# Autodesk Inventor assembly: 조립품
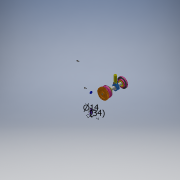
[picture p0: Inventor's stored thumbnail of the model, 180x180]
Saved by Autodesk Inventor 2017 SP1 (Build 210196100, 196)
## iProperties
Part Number: 조립품
Material: 일반
Document SubType Name: Assembly
Designer: 00-00
Author: 00-00
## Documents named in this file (21)
- C:\Users\00-00\Desktop\601206V1010\조립품.iam
- C:\Users\00-00\Desktop\601206V1010\E-링.ipt
- C:\Users\00-00\Desktop\601206V1010\개스킷 A.ipt
- C:\Users\00-00\Desktop\601206V1010\개스킷 B.ipt
- C:\Users\00-00\Desktop\601206V1010\덮개.ipt
- C:\Users\00-00\Desktop\601206V1010\뒤커버.ipt
- C:\Users\00-00\Desktop\601206V1010\링크.ipt
- C:\Users\00-00\Desktop\601206V1010\베어링 17 x 40 x 12.ipt
- C:\Users\00-00\Desktop\601206V1010\본체.ipt
- C:\Users\00-00\Desktop\601206V1010\볼트 M4 x 10.ipt
- C:\Users\00-00\Desktop\601206V1010\스퍼기어.ipt
- C:\Users\00-00\Desktop\601206V1010\슬라이더.ipt
- C:\Users\00-00\Desktop\601206V1010\앞커버.ipt
- C:\Users\00-00\Desktop\601206V1010\오일 실 17 30 8.ipt
- C:\Users\00-00\Desktop\601206V1010\와셔 4x16.ipt
- C:\Users\00-00\Desktop\601206V1010\육각 소켓 머리 볼트 M4 x 10.ipt
- C:\Users\00-00\Desktop\601206V1010\클레비스 핀 6 x 22.ipt
- 클레비스 핀 6 x 22.ipt
- C:\Users\00-00\Desktop\601206V1010\키 4 x 4 x 18.ipt
- C:\Users\00-00\Desktop\601206V1010\편심축.ipt
- C:\Users\00-00\Desktop\601206V1010\가변스프링.ipt
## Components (5 placed, 4 different names)
1. E-링:1
2. 개스킷 A:1
3. 개스킷 B:1
4. 가변스프링:1
5. 개스킷 A:2
